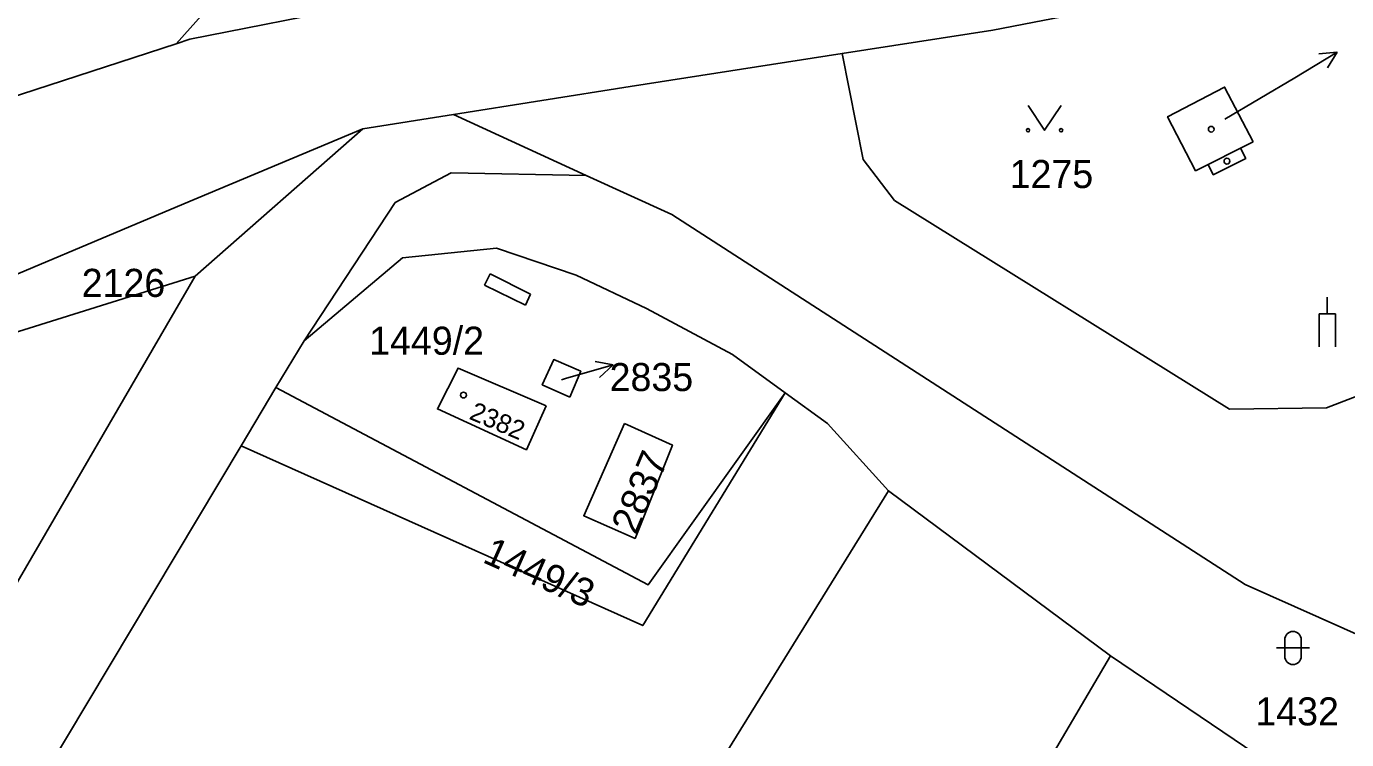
# Model space of a CAD drawing. Extents: x -679220 to -673243, y -1075091 to -1066557.
# Drawn here: x -677237.5 to -677157.5, y -1070793.9 to -1070750.8 of the extents above; entities that cross this region are included whole.
import ezdxf

# ---------------------------------------------------------------- set-up
doc = ezdxf.new("R2010")
doc.units = 0
for name, color, linetype in [('Hranice parcel', 7, 'Continuous'), ('Parcelní čísla', 7, 'Continuous'), ('Pop  PČ popisy', 7, 'Continuous'), ('Vnitřní kresba', 7, 'Continuous'), ('Značky budov', 7, 'Continuous'), ('Značky kultur', 7, 'Continuous')]:
    doc.layers.add(name, color=color, linetype=linetype)

msp = doc.modelspace()

# ---------------------------------------------------------------- linework, layer by layer
at = {"layer": 'Hranice parcel'}
for p, q in [((-677228.39, -1070751.81), (-677222.65, -1070745.38)), ((-677211.61, -1070756.1), (-677217.09, -1070756.97)), ((-677211.61, -1070756.1), (-677203.57, -1070759.78)), ((-677217.09, -1070756.97), (-677227.25, -1070765.88)), ((-677227.25, -1070765.88), (-677252.98, -1070810.18)), ((-677220.65, -1070769.8), (-677222.35, -1070772.63)), ((-677222.35, -1070772.63), (-677224.46, -1070776.16)), ((-677185.28, -1070778.87), (-677171.84, -1070788.87)), ((-677171.84, -1070788.87), (-677159.45, -1070797.23))]:
    msp.add_line(p, q, dxfattribs=at)
for points in [[(-677141.72, -1070742.83), (-677159.64, -1070747.23), (-677178.96, -1070751), (-677188.07, -1070752.41)], [(-677228.39, -1070751.81), (-677227.56, -1070751.54), (-677217.29, -1070749.51)], [(-677419.36, -1070901.45), (-677399.79, -1070883.04), (-677356.1, -1070840.53), (-677325.87, -1070810.52), (-677305.6, -1070792.25), (-677292.22, -1070782.24), (-677278.31, -1070773.02), (-677263.52, -1070765.35), (-677248.06, -1070758.21), (-677228.39, -1070751.81)], [(-677188.07, -1070752.41), (-677200.92, -1070754.41), (-677211.61, -1070756.1)], [(-677188.07, -1070752.41), (-677186.81, -1070758.82), (-677184.92, -1070761.3), (-677164.63, -1070773.94), (-677158.76, -1070773.85), (-677152.15, -1070771.31)], [(-677163.21, -1070757.75), (-677164.93, -1070754.44), (-677168.38, -1070756.23), (-677166.69, -1070759.5), (-677165.93, -1070759.12), (-677165.62, -1070759.74), (-677163.65, -1070758.76), (-677163.97, -1070758.13), (-677163.21, -1070757.75)], [(-677242.5, -1070767.63), (-677227.93, -1070761.51), (-677217.09, -1070756.97)], [(-677203.57, -1070759.78), (-677211.74, -1070759.63), (-677215.14, -1070761.43), (-677220.65, -1070769.8)], [(-677203.57, -1070759.78), (-677198.39, -1070762.15), (-677163.69, -1070784.55), (-677154.72, -1070788.54), (-677133.88, -1070803.28), (-677126.71, -1070808.28), (-677130.31, -1070813.04)], [(-677220.65, -1070769.8), (-677214.69, -1070764.78), (-677209, -1070764.18), (-677204.17, -1070765.82), (-677199.93, -1070767.85), (-677194.71, -1070770.62), (-677191.52, -1070772.94)], [(-677249.13, -1070775.06), (-677240.98, -1070770.18), (-677227.25, -1070765.88)], [(-677204.56, -1070773.2), (-677206.23, -1070772.46), (-677205.54, -1070770.93), (-677203.9, -1070771.64), (-677204.56, -1070773.2)], [(-677206, -1070773.74), (-677207.19, -1070776.39), (-677212.58, -1070773.92), (-677211.33, -1070771.45), (-677206, -1070773.74)], [(-677222.35, -1070772.63), (-677199.83, -1070784.57), (-677191.52, -1070772.94)], [(-677224.46, -1070776.16), (-677200.15, -1070787.03), (-677191.52, -1070772.94)], [(-677191.52, -1070772.94), (-677188.96, -1070774.81), (-677185.28, -1070778.87)], [(-677201.26, -1070774.81), (-677198.35, -1070776.11), (-677200.61, -1070781.76), (-677203.72, -1070780.39), (-677201.26, -1070774.81)], [(-677364.04, -1070987.23), (-677362.94, -1070980.54), (-677338.56, -1070950.82), (-677313.04, -1070919.03), (-677289.25, -1070883.76), (-677247.04, -1070813.86), (-677224.46, -1070776.16)], [(-677353.59, -1071009.21), (-677311.42, -1070962.52), (-677281.85, -1070927.39), (-677267.88, -1070909.25), (-677253.05, -1070888.24), (-677185.28, -1070778.87)], [(-677340.87, -1071024.47), (-677300.46, -1070979.79), (-677271.33, -1070945.13), (-677251.29, -1070919.02), (-677223.02, -1070875.98), (-677171.84, -1070788.87)]]:
    msp.add_lwpolyline(points, dxfattribs=at)
at = {"layer": 'Pop  PČ popisy'}
for p, q in [((-677160.68, -1070753.88), (-677158.108, -1070752.334)), ((-677158.108, -1070752.334), (-677159.224, -1070752.421)), ((-677158.108, -1070752.334), (-677158.708, -1070753.279)), ((-677164.92, -1070756.38), (-677160.68, -1070753.88)), ((-677201.935, -1070771.253), (-677203.036, -1070771.048)), ((-677204.82, -1070772.08), (-677201.935, -1070771.253)), ((-677201.935, -1070771.253), (-677202.76, -1070772.01)), ((-677205.07, -1070772.16), (-677204.82, -1070772.08))]:
    msp.add_line(p, q, dxfattribs=at)
at = {"layer": 'Vnitřní kresba'}
for p, q in [((-677165.93, -1070759.12), (-677163.97, -1070758.13)), ((-677209.72, -1070766.43), (-677209.39, -1070765.75)), ((-677209.39, -1070765.75), (-677206.94, -1070766.97)), ((-677207.24, -1070767.63), (-677209.72, -1070766.43)), ((-677206.94, -1070766.97), (-677207.24, -1070767.63))]:
    msp.add_line(p, q, dxfattribs=at)
at = {"layer": 'Značky budov'}
for centre in [(-677165.737, -1070756.989), (-677164.787, -1070758.919), (-677210.997, -1070773.079)]:
    msp.add_circle(centre, 0.175, dxfattribs=at)
at = {"layer": 'Značky kultur'}
for p, q in [((-677158.717, -1070768.16), (-677158.717, -1070767.158)), ((-677159.216, -1070768.16), (-677158.217, -1070768.16)), ((-677159.216, -1070770.16), (-677159.216, -1070768.16)), ((-677158.217, -1070770.16), (-677158.217, -1070768.16)), ((-677161.291, -1070787.891), (-677161.291, -1070788.892)), ((-677160.289, -1070788.892), (-677160.289, -1070787.891)), ((-677161.791, -1070788.391), (-677159.789, -1070788.391))]:
    msp.add_line(p, q, dxfattribs=at)
msp.add_lwpolyline([(-677176.83, -1070755.549), (-677175.83, -1070757.05), (-677174.83, -1070755.549)], dxfattribs=at)
for centre in [(-677176.83, -1070757.049), (-677174.83, -1070757.049)]:
    msp.add_circle(centre, 0.1, dxfattribs=at)
for centre, start, end in [((-677160.79, -1070787.891), 0, 180), ((-677160.79, -1070788.891), 180, 359.98789)]:
    msp.add_arc(centre, 0.5, start, end, dxfattribs=at)

# ---------------------------------------------------------------- texts
at = {"layer": 'Parcelní čísla'}
for s, p in [('1275', (-677177.94, -1070760.55)), ('2126', (-677234.11, -1070767.14)), ('1449/2', (-677216.71, -1070770.64)), ('2835', (-677202.154, -1070772.84)), ('1432', (-677163.07, -1070793.08))]:
    msp.add_text(s, height=1.7, dxfattribs=at).set_placement(p)
for s, height, rotation, p in [('2382', 1.139, 337, (-677210.716, -1070774.505)), ('2837', 1.7, 67, (-677200.549, -1070781.609)), ('1449/3', 1.7, 336, (-677209.915, -1070783.176))]:
    msp.add_text(s, height=height, rotation=rotation, dxfattribs=at).set_placement(p)

doc.saveas('drawing.dxf')
